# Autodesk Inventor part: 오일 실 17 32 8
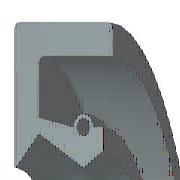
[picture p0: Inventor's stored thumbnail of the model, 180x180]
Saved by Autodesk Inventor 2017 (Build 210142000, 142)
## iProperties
IsCustomPart: 0
Created: 2018-09
Part Number: 오일 실 17 32 8
Material: 고무
Description: 오일-실
Document SubType Name: Modeling
Standard: KS B 2804
Standards Organization: KS
Language: ko-KR
Size Designation: D - 17 32 8
Categories: <MemberInstance><Categories><Category DisplayName="샤프트 부품" InternalName="7f7aeb1f-a693-4053-b835-cee3144e0d98" Mnemonic="SHFT"><Category DisplayName="실링" Intern
Density: 0.93 g/cm^3
Appearance: 고무 - 검은색 - 버전 1.1
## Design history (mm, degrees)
revolve "본체" stored, may be unused: angle "d17" = 90 deg
revolve "스프링1" stored, may be unused: angle "d18" = 90 deg
body "Solid1"
sketch "스케치1"
  geometry: L1 (0, 16)-(8, 16); L2 (8, 14.25)-(1.75, 14.25); L3 (1.75, 10.25)-(4.9, 8.5); L4 (4.9, 8.5)-(0, 8.5); L5 (0, 0)-(9.586, 0) reference; L6 (4.9, 8.5)-(6.3, 9.375); L7 (0, 18)-(0, -3) reference; L8 (-1.941, 0)-(11.507, 0) reference; L9 (4.2, 10.6)-(1.75, 11.21); L10 (1.75, 11.21)-(1.75, 14.25); L11 (0, 16)-(0, 8.588); L12 (4.9, 8.5)-(0, 8.5); L13 (1.75, 10.25)-(0.152, 8.528); L14 (8, 16)-(8, 14.25); L15 (5.6, 10.6)-(6.3, 10.6); L16 (6.3, 10.6)-(6.3, 9.375); C1 r 0.455 at (4.9, 10.6); A1 r 0.7 centre (4.9, 10.6) between (5.6, 10.6) and (4.2, 10.6); A2 r 0.088 centre (0.088, 8.588) between (0, 8.588) and (0.152, 8.528); 1 further point
  constraints: 28 end point, 5 horizontal alignment, 5 point on line, 4 point on circle, 4 vertical alignment, 3 centre point, 3 tangent, 2 collinear, 2 horizontal, 2 perpendicular, 1 coincident, 1 parallel
  dimensions: "d0" = 32 diameter of L1 L5 (= SD2); "d1" = 1.75 distance of L1.end L2.start (= SD); "d2" = 0.91 diameter of C1 (= SPDI); "d3" = 1.4 diameter of A1 (= SPDA); "d4" = 17 diameter of L3.end L5 (= NND); "d5" = 20.5 diameter of L3.start L5 (= TKDM); "d7" = 22.42 diameter of L9.end L5 (= TKDM + 0.24 x SWDT); "d8" = 1.75 distance between parallel lines of L11 L10 (= SD); "d9" = 4.9 distance from line of L11 C1.centre (= SPDST); "d10" = 21.2 diameter of C1.centre L5 (= HLDM); "d11" = 0.0875 radius of A2 (= 0.25 x LAB); "d12" = 6.3 distance between parallel lines of L11 L16 (= SDI); "d13" = 18.75 diameter of L6.end L5 (= ABDM); "d14" = 8 distance from line of L11 L1.end (= SWDT)
fillet "모깎기1" dims "d6" = 0.3 (= RR)
other parameters: "SD2" = 32 [user parameter; used in 1 equation term], "SWDT" = 8 [user parameter; used in 2 equation terms], "RR" = 0.3 [user parameter; used in 1 equation term], "SD" = 1.75 [user parameter; used in 2 equation terms], "NND" = 17 [user parameter; used in 1 equation term], "SPDA" = 1.4 [user parameter; used in 1 equation term], "SPDI" = 0.91 [user parameter; used in 1 equation term], "TKDM" = 20.5 [user parameter; used in 2 equation terms], "HLDM" = 21.2 [user parameter; used in 1 equation term], "ABDM" = 18.75 [user parameter; used in 1 equation term], "SDI" = 6.3 [user parameter; used in 1 equation term], "SPDST" = 4.9 [user parameter; used in 1 equation term], "LAB" = 0.35 [user parameter; used in 1 equation term], "d15" = 0, "d16" = 0, "d19" = 0
